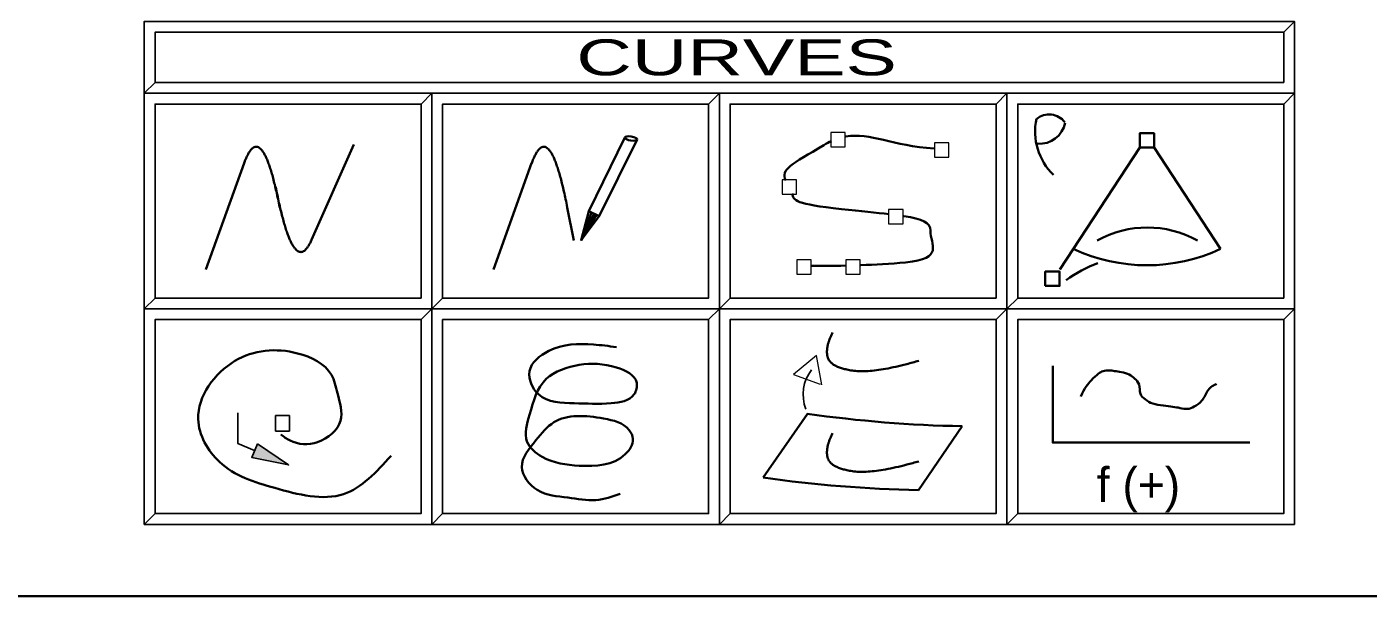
# Model space of a CAD drawing. Extents: x 95906.8 to 95923.6, y 90964.8 to 90972.8.
# Drawn here: x 95914.366 to 95916.232, y 90964.762 to 90965.554 of the extents above; entities that cross this region are included whole.
import ezdxf
from ezdxf.enums import TextEntityAlignment as Align

# ---------------------------------------------------------------- set-up
doc = ezdxf.new("R2010")
doc.units = 0
doc.header["$LTSCALE"] = 0.019
for name, color, linetype, lineweight in [('1', 7, 'Continuous', 25), ('11', 7, 'Continuous', 25), ('12', 7, 'Continuous', 25), ('17', 7, 'Continuous', 25), ('2', 7, 'Continuous', 13), ('3', 7, 'Continuous', 25), ('6', 7, 'Continuous', 35), ('7', 7, 'Continuous', 35)]:
    doc.layers.add(name, color=color, linetype=linetype, lineweight=lineweight)

msp = doc.modelspace()

# ---------------------------------------------------------------- hatches: boundary and pattern name
at = {"layer": '6'}
msp.add_hatch(color=256, dxfattribs=at).paths.add_polyline_path([(95914.6873, 90964.9736), (95914.7305, 90964.9443), (95914.6794, 90964.9549)])

# ---------------------------------------------------------------- linework, layer by layer
at = {"layer": '1'}
for points in [[(95914.5298, 90965.4617), (95916.1298, 90965.4617), (95916.1298, 90965.5617), (95914.5298, 90965.5617)], [(95914.5298, 90965.1617), (95914.9298, 90965.1617), (95914.9298, 90965.4617), (95914.5298, 90965.4617)], [(95914.9298, 90965.1617), (95915.3298, 90965.1617), (95915.3298, 90965.4617), (95914.9298, 90965.4617)], [(95915.3298, 90965.1617), (95915.7298, 90965.1617), (95915.7298, 90965.4617), (95915.3298, 90965.4617)], [(95915.7298, 90965.1617), (95916.1298, 90965.1617), (95916.1298, 90965.4617), (95915.7298, 90965.4617)], [(95914.5298, 90964.8617), (95914.9298, 90964.8617), (95914.9298, 90965.1617), (95914.5298, 90965.1617)], [(95914.9298, 90964.8617), (95915.3298, 90964.8617), (95915.3298, 90965.1617), (95914.9298, 90965.1617)], [(95915.3298, 90964.8617), (95915.7298, 90964.8617), (95915.7298, 90965.1617), (95915.3298, 90965.1617)], [(95915.7298, 90964.8617), (95916.1298, 90964.8617), (95916.1298, 90965.1617), (95915.7298, 90965.1617)]]:
    msp.add_lwpolyline(points, close=True, dxfattribs=at)
at = {"layer": '11'}
for points in [[(95914.9448, 90965.1767), (95915.3148, 90965.1767), (95915.3148, 90965.4467), (95914.9448, 90965.4467)], [(95915.3448, 90965.1767), (95915.7148, 90965.1767), (95915.7148, 90965.4467), (95915.3448, 90965.4467)], [(95915.7448, 90965.1767), (95916.1148, 90965.1767), (95916.1148, 90965.4467), (95915.7448, 90965.4467)], [(95914.5448, 90964.8767), (95914.9148, 90964.8767), (95914.9148, 90965.1467), (95914.5448, 90965.1467)], [(95914.9448, 90964.8767), (95915.3148, 90964.8767), (95915.3148, 90965.1467), (95914.9448, 90965.1467)], [(95915.3448, 90964.8767), (95915.7148, 90964.8767), (95915.7148, 90965.1467), (95915.3448, 90965.1467)], [(95915.7448, 90964.8767), (95916.1148, 90964.8767), (95916.1148, 90965.1467), (95915.7448, 90965.1467)]]:
    msp.add_lwpolyline(points, close=True, dxfattribs=at)
at = {"layer": '12'}
msp.add_lwpolyline([(95914.5448, 90965.1767), (95914.9148, 90965.1767), (95914.9148, 90965.4467), (95914.5448, 90965.4467)], close=True, dxfattribs=at)
at = {"layer": '17'}
msp.add_lwpolyline([(95914.5448, 90965.4767), (95916.1148, 90965.4767), (95916.1148, 90965.5467), (95914.5448, 90965.5467)], close=True, dxfattribs=at)
at = {"layer": '2'}
for points in [[(95914.5298, 90965.5617), (95914.5298, 90965.4617), (95914.5448, 90965.4767), (95914.5448, 90965.5467), (95916.1148, 90965.5467), (95916.1298, 90965.5617)], [(95914.5298, 90965.4617), (95914.5298, 90965.1617), (95914.5448, 90965.1767), (95914.5448, 90965.4467), (95914.9148, 90965.4467), (95914.9298, 90965.4617)], [(95914.9298, 90965.4617), (95914.9298, 90965.1617), (95914.9448, 90965.1767), (95914.9448, 90965.4467), (95915.3148, 90965.4467), (95915.3298, 90965.4617)], [(95915.3298, 90965.4617), (95915.3298, 90965.1617), (95915.3448, 90965.1767), (95915.3448, 90965.4467), (95915.7148, 90965.4467), (95915.7298, 90965.4617)], [(95915.7298, 90965.4617), (95915.7298, 90965.1617), (95915.7448, 90965.1767), (95915.7448, 90965.4467), (95916.1148, 90965.4467), (95916.1298, 90965.4617)], [(95914.5298, 90965.1617), (95914.5298, 90964.8617), (95914.5448, 90964.8767), (95914.5448, 90965.1467), (95914.9148, 90965.1467), (95914.9298, 90965.1617)], [(95914.9298, 90965.1617), (95914.9298, 90964.8617), (95914.9448, 90964.8767), (95914.9448, 90965.1467), (95915.3148, 90965.1467), (95915.3298, 90965.1617)], [(95915.3298, 90965.1617), (95915.3298, 90964.8617), (95915.3448, 90964.8767), (95915.3448, 90965.1467), (95915.7148, 90965.1467), (95915.7298, 90965.1617)], [(95915.7298, 90965.1617), (95915.7298, 90964.8617), (95915.7448, 90964.8767), (95915.7448, 90965.1467), (95916.1148, 90965.1467), (95916.1298, 90965.1617)]]:
    msp.add_lwpolyline(points, close=True, dxfattribs=at)
at = {"layer": '3'}
for points in [[(95914.5298, 90965.4617), (95916.1298, 90965.4617), (95916.1298, 90965.5617), (95916.1148, 90965.5467), (95916.1148, 90965.4767), (95914.5448, 90965.4767)], [(95914.5298, 90965.1617), (95914.9298, 90965.1617), (95914.9298, 90965.4617), (95914.9148, 90965.4467), (95914.9148, 90965.1767), (95914.5448, 90965.1767)], [(95914.9298, 90965.1617), (95915.3298, 90965.1617), (95915.3298, 90965.4617), (95915.3148, 90965.4467), (95915.3148, 90965.1767), (95914.9448, 90965.1767)], [(95915.3298, 90965.1617), (95915.7298, 90965.1617), (95915.7298, 90965.4617), (95915.7148, 90965.4467), (95915.7148, 90965.1767), (95915.3448, 90965.1767)], [(95915.7298, 90965.1617), (95916.1298, 90965.1617), (95916.1298, 90965.4617), (95916.1148, 90965.4467), (95916.1148, 90965.1767), (95915.7448, 90965.1767)], [(95914.5298, 90964.8617), (95914.9298, 90964.8617), (95914.9298, 90965.1617), (95914.9148, 90965.1467), (95914.9148, 90964.8767), (95914.5448, 90964.8767)], [(95914.9298, 90964.8617), (95915.3298, 90964.8617), (95915.3298, 90965.1617), (95915.3148, 90965.1467), (95915.3148, 90964.8767), (95914.9448, 90964.8767)], [(95915.3298, 90964.8617), (95915.7298, 90964.8617), (95915.7298, 90965.1617), (95915.7148, 90965.1467), (95915.7148, 90964.8767), (95915.3448, 90964.8767)], [(95915.7298, 90964.8617), (95916.1298, 90964.8617), (95916.1298, 90965.1617), (95916.1148, 90965.1467), (95916.1148, 90964.8767), (95915.7448, 90964.8767)]]:
    msp.add_lwpolyline(points, close=True, dxfattribs=at)
at = {"layer": '6'}
for p, q in [((95915.1984, 90965.4), (95915.1481, 90965.2978)), ((95915.2153, 90965.3973), (95915.1628, 90965.2906)), ((95914.7626, 90965.2577), (95914.8214, 90965.3905)), ((95915.9146, 90965.3861), (95915.8035, 90965.2166)), ((95915.9346, 90965.3861), (95916.0271, 90965.245)), ((95914.6154, 90965.2162), (95914.6687, 90965.3644)), ((95915.0154, 90965.2162), (95915.0687, 90965.3644)), ((95915.1182, 90965.3029), (95915.1276, 90965.2569)), ((95915.1374, 90965.2574), (95915.152, 90965.2959)), ((95915.1555, 90965.2942), (95915.1374, 90965.2574)), ((95915.4522, 90965.0154), (95915.3909, 90964.9269)), ((95915.6677, 90964.9983), (95915.6067, 90964.9094))]:
    msp.add_line(p, q, dxfattribs=at)
at = {"layer": '6', "lineweight": 13}
msp.add_line((95915.433, 90965.0701), (95915.4702, 90965.0566), dxfattribs=at)
for points in [[(95915.485, 90965.3871), (95915.505, 90965.3871), (95915.505, 90965.4071), (95915.485, 90965.4071)], [(95915.6291, 90965.3727), (95915.6491, 90965.3727), (95915.6491, 90965.3927), (95915.6291, 90965.3927)], [(95915.417, 90965.3212), (95915.437, 90965.3212), (95915.437, 90965.3412), (95915.417, 90965.3412)], [(95915.5653, 90965.28), (95915.5853, 90965.28), (95915.5853, 90965.3), (95915.5653, 90965.3)], [(95915.4377, 90965.2098), (95915.4577, 90965.2098), (95915.4577, 90965.2298), (95915.4377, 90965.2298)], [(95915.5056, 90965.2098), (95915.5256, 90965.2098), (95915.5256, 90965.2298), (95915.5056, 90965.2298)]]:
    msp.add_lwpolyline(points, close=True, dxfattribs=at)
at = {"layer": '6'}
for points in [[(95915.9146, 90965.3861), (95915.9346, 90965.3861), (95915.9346, 90965.4061), (95915.9146, 90965.4061)], [(95915.9146, 90965.3861), (95915.9346, 90965.3861), (95915.9346, 90965.4061), (95915.9146, 90965.4061)], [(95915.783, 90965.1936), (95915.803, 90965.1936), (95915.803, 90965.2136), (95915.783, 90965.2136)]]:
    msp.add_lwpolyline(points, close=True, dxfattribs=at)
for points in [[(95915.1481, 90965.2978), (95915.1628, 90965.2906), (95915.1374, 90965.2574)], [(95915.1481, 90965.2978), (95915.1374, 90965.2574), (95915.159, 90965.2923)], [(95916.0679, 90964.9754), (95915.7936, 90964.9754), (95915.7936, 90965.0824)]]:
    msp.add_lwpolyline(points, dxfattribs=at)
at = {"layer": '6', "lineweight": 13}
msp.add_lwpolyline([(95915.4722, 90965.0558), (95915.4649, 90965.0968), (95915.433, 90965.0701)], dxfattribs=at)
at = {"layer": '6', "lineweight": 25}
msp.add_lwpolyline([(95914.6602, 90965.0167), (95914.6602, 90964.9741), (95914.6834, 90964.9643)], dxfattribs=at)
for points in [[(95914.7126, 90965.0131), (95914.7318, 90965.0131), (95914.7318, 90964.9915), (95914.7126, 90964.9915)], [(95914.6873, 90964.9736), (95914.7305, 90964.9443), (95914.6794, 90964.9549)]]:
    msp.add_lwpolyline(points, close=True, dxfattribs=at)
at = {"layer": '6'}
for centre, radius, start, end in [((95915.7885, 90965.4053), 0.027, 36.5372, 129.7193), ((95915.8539, 90965.4087), 0.0849, 168.1659, 225.5957), ((95915.7748, 90965.4283), 0.037, 266.271, 347.9424), ((95915.9251, 90965.1334), 0.1415, 60.5317, 119.4682), ((95915.9246, 90965.4646), 0.2423, 244.9787, 295.0213), ((95915.9107, 90965.0697), 0.1646, 109.2772, 126.814), ((95915.6994, 90966.7405), 1.7425, 261.8343, 268.9564), ((95915.6384, 90966.6516), 1.7425, 261.8343, 268.9564)]:
    msp.add_arc(centre, radius, start, end, dxfattribs=at)
at = {"layer": '6', "lineweight": 25}
msp.add_arc((95915.5018, 90965.0426), 0.0555, 141.7923, 201.5664, dxfattribs=at)
at = {"layer": '6'}
msp.add_ellipse((95915.2069, 90965.3987), major_axis=(0.00845, -0.00135), ratio=0.335575, dxfattribs=at)
for points, degree in [([(95915.4857, 90965.3951), (95915.4823, 90965.3936), (95915.4787, 90965.3917), (95915.4751, 90965.3895)], 3), ([(95915.6285, 90965.3847), (95915.5707, 90965.3884), (95915.5399, 90965.4073), (95915.5057, 90965.4015)], 3), ([(95915.4751, 90965.3895), (95915.4303, 90965.3626), (95915.4139, 90965.3559), (95915.4223, 90965.3402)], 3), ([(95915.4312, 90965.322), (95915.4331, 90965.3123), (95915.4347, 90965.3077), (95915.4998, 90965.3005)], 3), ([(95915.4998, 90965.3005), (95915.5266, 90965.2975), (95915.5484, 90965.2954), (95915.5659, 90965.2934)], 3), ([(95915.5865, 90965.2907), (95915.6123, 90965.2868), (95915.6234, 90965.2819), (95915.6234, 90965.2707)], 3), ([(95915.6234, 90965.2707), (95915.6234, 90965.251), (95915.6433, 90965.2314), (95915.5889, 90965.2263)], 3), ([(95915.5889, 90965.2263), (95915.5674, 90965.2243), (95915.546, 90965.2231), (95915.5264, 90965.2224)], 3), ([(95915.5058, 90965.2218), (95915.4864, 90965.2213), (95915.4699, 90965.2213), (95915.4585, 90965.2213)], 3), ([(95915.4872, 90965.1286), (95915.4764, 90965.107), (95915.4849, 90965.0803), (95915.5446, 90965.0711), (95915.6072, 90965.0894)], 2), ([(95915.8328, 90965.0395), (95915.8378, 90965.0512), (95915.8476, 90965.0638), (95915.8577, 90965.0716), (95915.8631, 90965.0757), (95915.8722, 90965.0762), (95915.8791, 90965.0752), (95915.8888, 90965.0738), (95915.9006, 90965.0709), (95915.9076, 90965.0645), (95915.9149, 90965.0578), (95915.914, 90965.0417), (95915.9218, 90965.036), (95915.9318, 90965.0287), (95915.9477, 90965.0274), (95915.961, 90965.0253), (95915.9703, 90965.0238), (95915.9817, 90965.0212), (95915.9895, 90965.0253), (95916.0019, 90965.0319), (95916.0093, 90965.0505), (95916.0177, 90965.0552), (95916.021, 90965.0571), (95916.0212, 90965.0572)], 3), ([(95915.4872, 90964.9886), (95915.4764, 90964.967), (95915.4849, 90964.9403), (95915.5446, 90964.9311), (95915.6072, 90964.9494)], 2)]:
    msp.add_open_spline(points, degree=degree, dxfattribs=at)
for points in [[(95914.7182, 90965.3029), (95914.7159, 90965.3143), (95914.7136, 90965.3249), (95914.7113, 90965.3345), (95914.7091, 90965.3435), (95914.7068, 90965.3516), (95914.7045, 90965.3588), (95914.7022, 90965.3653), (95914.7, 90965.3709), (95914.6977, 90965.3757), (95914.6954, 90965.3796), (95914.6932, 90965.3827), (95914.6909, 90965.385), (95914.6886, 90965.3865), (95914.6863, 90965.3872), (95914.6841, 90965.387), (95914.6818, 90965.3861), (95914.6795, 90965.3843), (95914.6772, 90965.3817), (95914.675, 90965.3782), (95914.6727, 90965.3739), (95914.6704, 90965.3689), (95914.6682, 90965.3629)], [(95915.1182, 90965.3029), (95915.1159, 90965.3143), (95915.1136, 90965.3249), (95915.1113, 90965.3345), (95915.1091, 90965.3435), (95915.1068, 90965.3516), (95915.1045, 90965.3588), (95915.1022, 90965.3653), (95915.1, 90965.3709), (95915.0977, 90965.3757), (95915.0954, 90965.3796), (95915.0932, 90965.3827), (95915.0909, 90965.385), (95915.0886, 90965.3865), (95915.0863, 90965.3872), (95915.0841, 90965.387), (95915.0818, 90965.3861), (95915.0795, 90965.3843), (95915.0772, 90965.3817), (95915.075, 90965.3782), (95915.0727, 90965.3739), (95915.0704, 90965.3689), (95915.0682, 90965.3629)], [(95914.7627, 90965.2578), (95914.7604, 90965.253), (95914.7581, 90965.2491), (95914.7559, 90965.2459), (95914.7536, 90965.2434), (95914.7513, 90965.2417), (95914.7491, 90965.2409), (95914.7468, 90965.2408), (95914.7445, 90965.2414), (95914.7422, 90965.2428), (95914.74, 90965.245), (95914.7377, 90965.248), (95914.7354, 90965.2517), (95914.7331, 90965.2562), (95914.7309, 90965.2615), (95914.7286, 90965.2675), (95914.7263, 90965.2743), (95914.7241, 90965.2819), (95914.7218, 90965.2903), (95914.7195, 90965.2994), (95914.7172, 90965.3093), (95914.715, 90965.32), (95914.7127, 90965.3314)], [(95915.1865, 90965.1084), (95915.1546, 90965.112), (95915.0924, 90965.1031), (95915.0658, 90965.0747), (95915.0782, 90965.0427), (95915.1279, 90965.0303), (95915.1794, 90965.0303), (95915.2114, 90965.0427), (95915.2149, 90965.0587), (95915.1865, 90965.08), (95915.135, 90965.0836), (95915.0889, 90965.064), (95915.0658, 90965.0143), (95915.0622, 90964.977), (95915.0835, 90964.9557), (95915.135, 90964.9433), (95915.199, 90964.9593), (95915.2096, 90964.9806), (95915.2043, 90964.993), (95915.1688, 90965.009), (95915.0995, 90965.0037), (95915.0747, 90964.9788), (95915.0551, 90964.9415), (95915.0764, 90964.9096), (95915.1191, 90964.8989), (95915.1581, 90964.8954), (95915.1919, 90964.9042)], [(95914.7198, 90964.9869), (95914.7326, 90964.9783), (95914.7709, 90964.9762), (95914.8029, 90965.006), (95914.7986, 90965.0443), (95914.7901, 90965.0699), (95914.7432, 90965.0997), (95914.6559, 90965.0891), (95914.6048, 90965.0081), (95914.6346, 90964.9485), (95914.7113, 90964.9123), (95914.8071, 90964.9038), (95914.8731, 90964.957)]]:
    msp.add_spline(points, degree=3, dxfattribs=at)
at = {"layer": '7'}
msp.add_lwpolyline([(95906.8323, 90972.7617), (95918.8323, 90972.7617), (95918.8323, 90964.7617), (95906.8323, 90964.7617)], close=True, dxfattribs=at)

# ---------------------------------------------------------------- texts
at = {"layer": '6'}
msp.add_text('f (+)', height=0.048, dxfattribs=at).set_placement((95915.9128, 90964.8929), align=Align.CENTER)
at = {"layer": '7', "width": 1.6}
msp.add_text('      CURVES     ', height=0.05, dxfattribs=at).set_placement((95915.3389, 90965.4867), align=Align.CENTER)

doc.saveas('drawing.dxf')
